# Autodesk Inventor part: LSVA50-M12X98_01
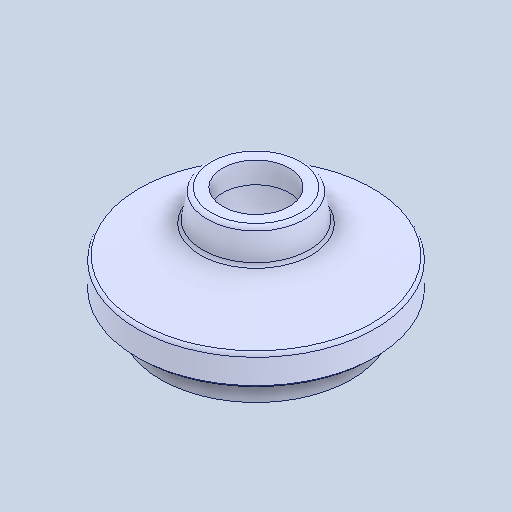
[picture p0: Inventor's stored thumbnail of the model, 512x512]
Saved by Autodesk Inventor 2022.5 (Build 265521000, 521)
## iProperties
Created: 2024-08
Part Number: LSVA50-M12X98_01
Material: 一般
Document SubType Name: Modeling
Designer: ImaoCorp
Density: 1 g/cm^3
Appearance: 既定
Author: ImaoCorp
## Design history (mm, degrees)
feature "LSVA50-M12X98_01"
node "ソリッド1"
